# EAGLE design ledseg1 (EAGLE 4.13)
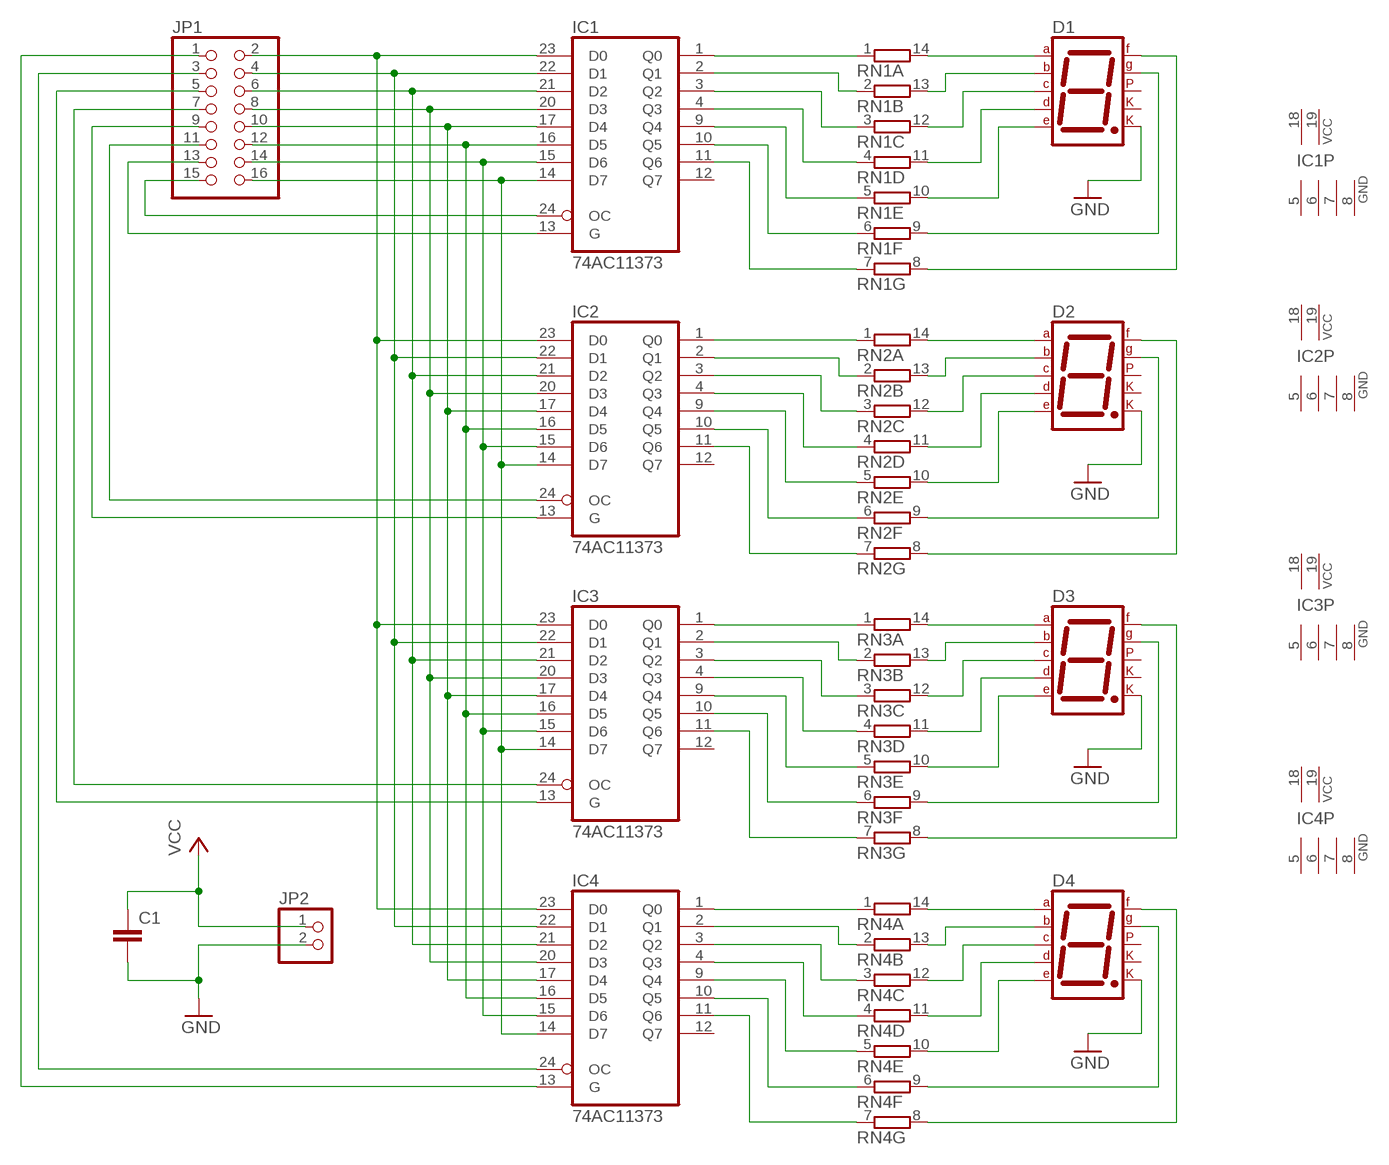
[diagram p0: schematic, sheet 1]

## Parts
C1  C-EU025-030X050  [C025-030X050]
D1  7SEG-CK  [7SEG-13]
D2  7SEG-CK  [7SEG-13]
D3  7SEG-CK  [7SEG-13]
D4  7SEG-CK  [7SEG-13]
IC1  74AC11373  [DIL24-6]
IC2  74AC11373  [DIL24-6]
IC3  74AC11373  [DIL24-6]
IC4  74AC11373  [DIL24-6]
JP1  PINHD-2X8  [2X08]
JP2  PINHD-1X2  [1X02]
RN1  7R-N  [DIL14]
RN2  7R-N  [DIL14]
RN3  7R-N  [DIL14]
RN4  7R-N  [DIL14]

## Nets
D0: IC1.23(D0) IC2.23(D0) IC3.23(D0) IC4.23(D0) JP1.2
D1: IC1.22(D1) IC2.22(D1) IC3.22(D1) IC4.22(D1) JP1.4
D2: IC1.21(D2) IC2.21(D2) IC3.21(D2) IC4.21(D2) JP1.6
D3: IC1.20(D3) IC2.20(D3) IC3.20(D3) IC4.20(D3) JP1.8
D4: IC1.17(D4) IC2.17(D4) IC3.17(D4) IC4.17(D4) JP1.10
D5: IC1.16(D5) IC2.16(D5) IC3.16(D5) IC4.16(D5) JP1.12
D6: IC1.15(D6) IC2.15(D6) IC3.15(D6) IC4.15(D6) JP1.14
D7: IC1.14(D7) IC2.14(D7) IC3.14(D7) IC4.14(D7) JP1.16
GND: C1.2 D1.8(CK2) D2.8(CK2) D3.8(CK2) D4.8(CK2) JP2.2
N$1: D1.7(A) RN1.14
N$2: D1.6(B) RN1.13
N$3: D1.4(C) RN1.12
N$4: D1.2(D) RN1.11
N$5: D1.1(E) RN1.10
N$6: D1.10(G) RN1.9
N$7: D1.9(F) RN1.8
N$8: D2.7(A) RN2.14
N$9: D2.6(B) RN2.13
N$10: D2.4(C) RN2.12
N$11: D2.2(D) RN2.11
N$12: D2.1(E) RN2.10
N$13: D2.10(G) RN2.9
N$14: D2.9(F) RN2.8
N$15: D3.7(A) RN3.14
N$16: D3.6(B) RN3.13
N$17: D3.4(C) RN3.12
N$18: D3.2(D) RN3.11
N$19: D3.1(E) RN3.10
N$20: D3.10(G) RN3.9
N$21: D3.9(F) RN3.8
N$22: D4.7(A) RN4.14
N$23: D4.6(B) RN4.13
N$24: D4.4(C) RN4.12
N$25: D4.2(D) RN4.11
N$26: D4.1(E) RN4.10
N$27: D4.10(G) RN4.9
N$28: D4.9(F) RN4.8
N$29: IC4.1(Q0) RN4.1
N$30: IC4.2(Q1) RN4.2
N$31: IC4.3(Q2) RN4.3
N$32: IC1.1(Q0) RN1.1
N$33: IC1.2(Q1) RN1.2
N$34: IC1.3(Q2) RN1.3
N$35: IC1.4(Q3) RN1.4
N$36: IC1.9(Q4) RN1.5
N$37: IC1.10(Q5) RN1.6
N$38: IC1.11(Q6) RN1.7
N$39: IC2.1(Q0) RN2.1
N$40: IC2.2(Q1) RN2.2
N$41: IC2.3(Q2) RN2.3
N$42: IC2.4(Q3) RN2.4
N$43: IC2.9(Q4) RN2.5
N$44: IC2.10(Q5) RN2.6
N$45: IC2.11(Q6) RN2.7
N$46: IC3.1(Q0) RN3.1
N$47: IC3.2(Q1) RN3.2
N$48: IC3.3(Q2) RN3.3
N$49: IC3.4(Q3) RN3.4
N$50: IC3.9(Q4) RN3.5
N$51: IC3.10(Q5) RN3.6
N$52: IC3.11(Q6) RN3.7
N$53: IC4.4(Q3) RN4.4
N$54: IC4.9(Q4) RN4.5
N$55: IC4.10(Q5) RN4.6
N$56: IC4.11(Q6) RN4.7
N$57: IC2.24(OC) JP1.11
N$58: IC2.13(G) JP1.9
N$59: IC3.24(OC) JP1.7
N$60: IC3.13(G) JP1.5
N$61: IC4.24(OC) JP1.3
N$62: IC4.13(G) JP1.1
N$65: IC1.24(OC) JP1.15
N$66: IC1.13(G) JP1.13
VCC: C1.1 JP2.1
Unconnected: D1.3(CK1) D1.5(DP) D2.3(CK1) D2.5(DP) D3.3(CK1) D3.5(DP) D4.3(CK1) D4.5(DP) IC1.12(Q7) IC2.12(Q7) IC3.12(Q7) IC4.12(Q7)

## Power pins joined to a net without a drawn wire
GND: IC1.5(GND) IC1.6(GND) IC1.7(GND) IC1.8(GND) IC2.5(GND) IC2.6(GND) IC2.7(GND) IC2.8(GND) IC3.5(GND) IC3.6(GND) IC3.7(GND) IC3.8(GND) IC4.5(GND) IC4.6(GND) IC4.7(GND) IC4.8(GND)
VCC: IC1.18(VCC) IC1.19(VCC) IC2.18(VCC) IC2.19(VCC) IC3.18(VCC) IC3.19(VCC) IC4.18(VCC) IC4.19(VCC)

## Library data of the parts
C1 = rcl:C-EU: CAPACITOR, European symbol
D1-D4 = special:7SEG-CK: 7-segment DISPLAY single cathode, 13 mm
IC1-IC4 = 74ac-logic:74AC11373: Octal transparent D-type LATCH, 3-state
JP1 = pinhead:PINHD-2X8: PIN HEADER
JP2 = pinhead:PINHD-1X2: PIN HEADER
RN1-RN4 = resistor-dil:7R-N: DIL RESISTOR

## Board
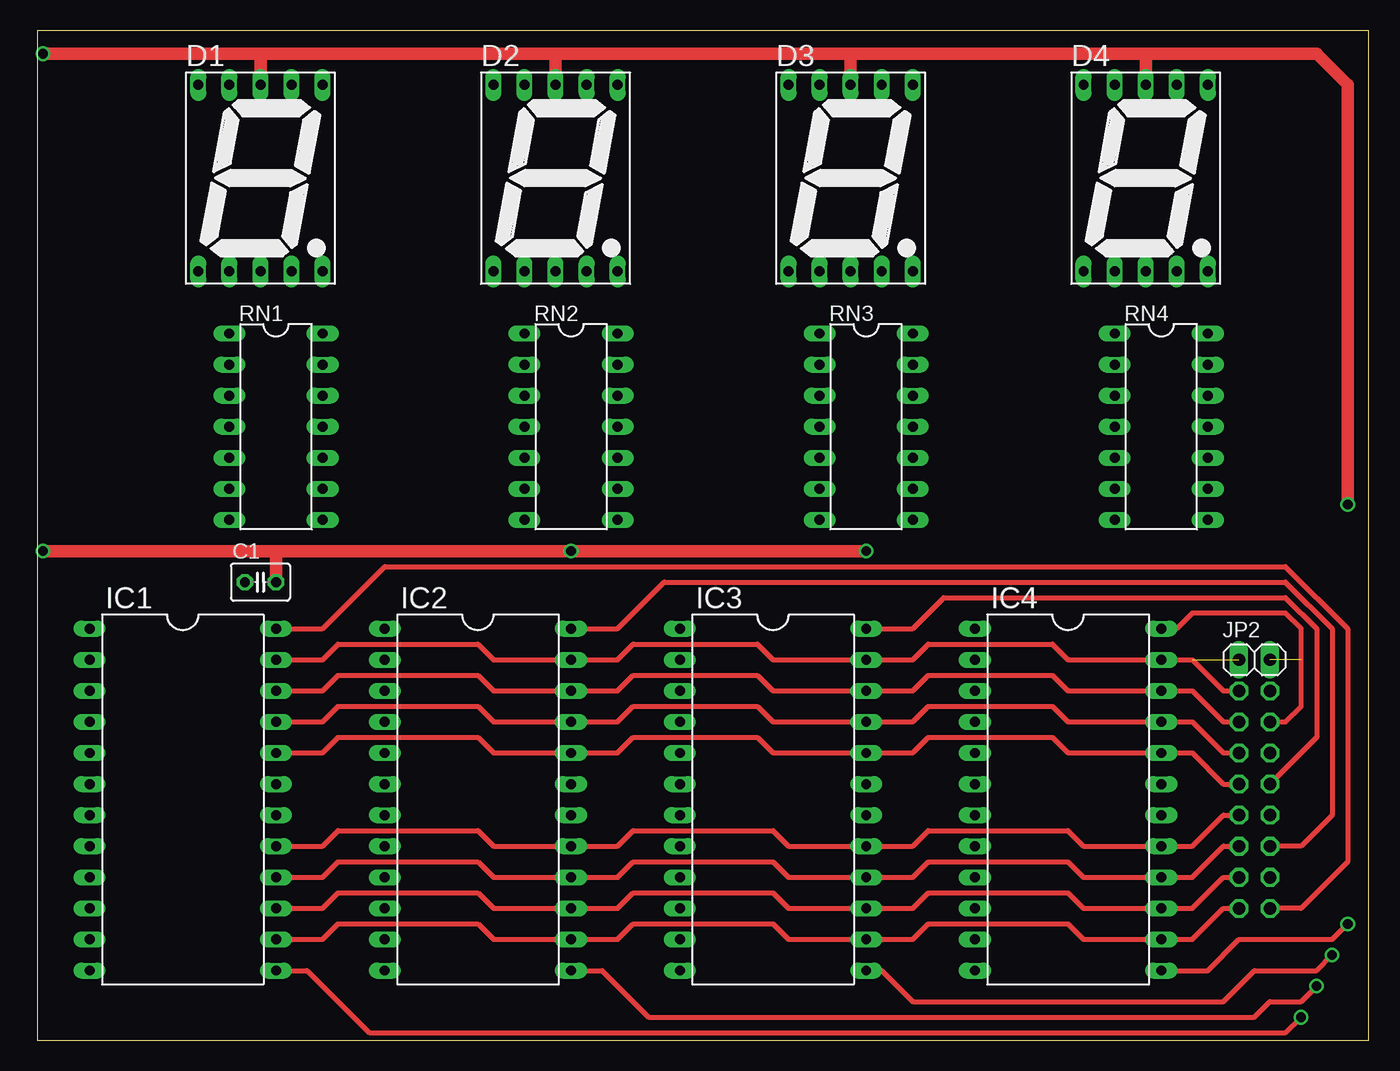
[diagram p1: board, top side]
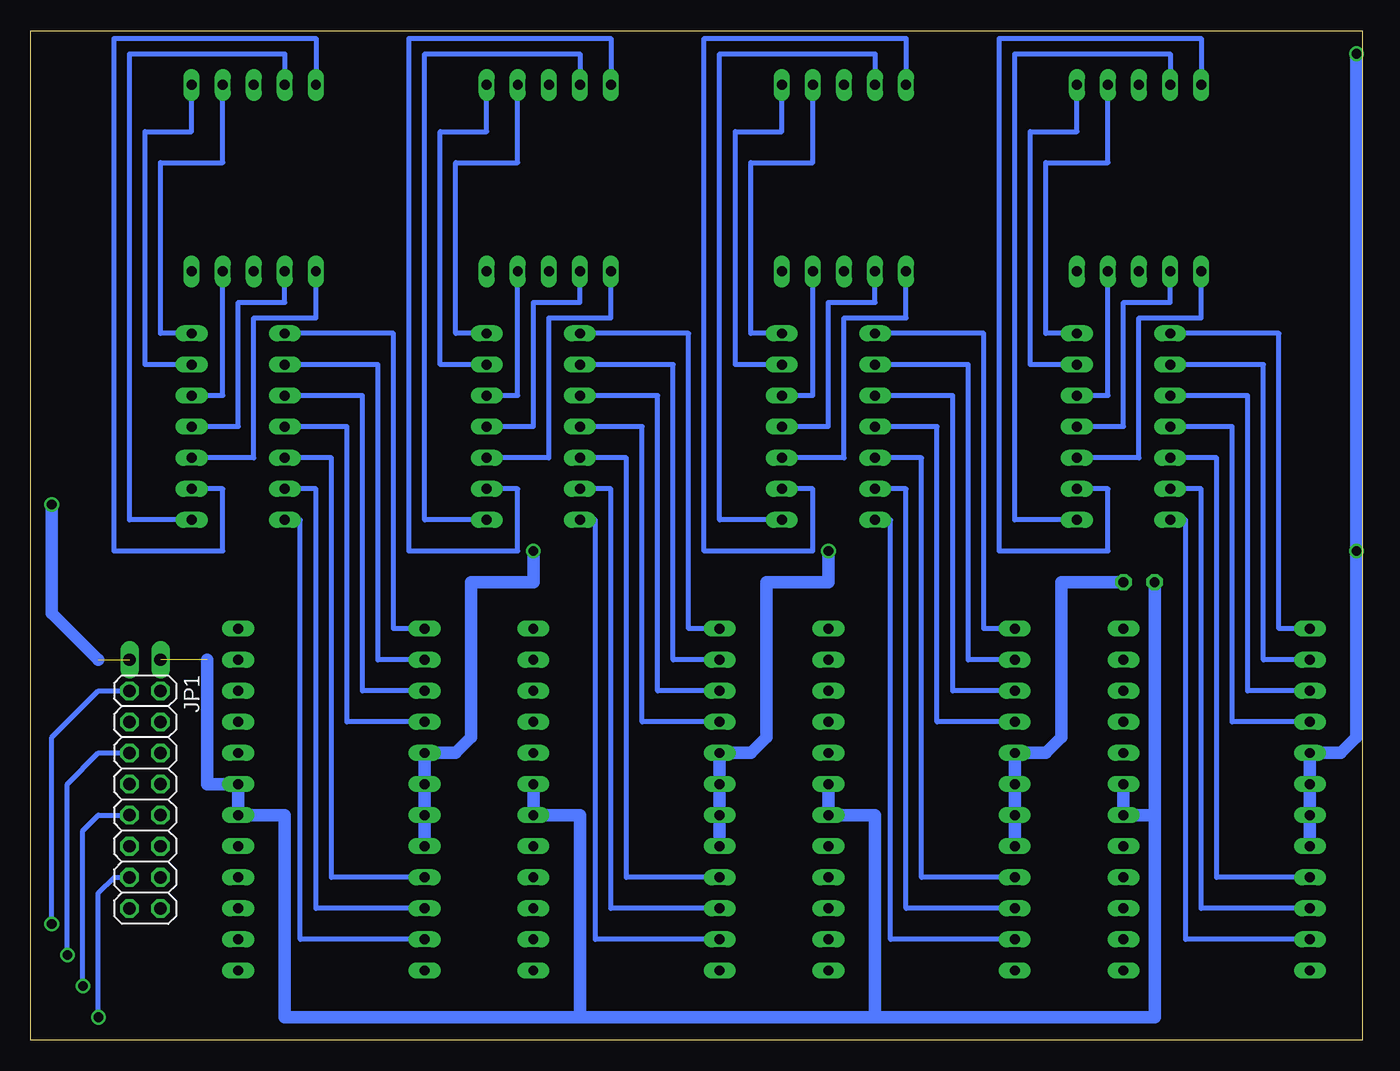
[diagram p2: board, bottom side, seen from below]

Size 108.89 x 82.54 mm. Coordinates in mm from the lower left corner, seen from the top.
Outline: 0,0 108.89,0 108.89,82.54 0,82.54 0,0
Copper layers (1*16): Top 0.035mm / dielectric 1.5mm / Bottom 0.035mm
Design rules "default": minimum track width 10mil, minimum drill 24mil, track to track 8mil, track to pad 8mil, pad to pad 8mil, via to via 8mil, smd to smd 8mil, copper to edge 40mil, drill to drill 8mil, minimum pad ring 10mil, minimum via ring 8mil, stop-mask expansion 4mil, vias tented up to drill 0mil, thermal gap 10mil

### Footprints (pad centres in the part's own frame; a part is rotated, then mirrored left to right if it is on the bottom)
C025-030X050 = drill 0.813 octagon: 1 -1.27,0; 2 1.27,0
7SEG-13 = drill 0.813 long: 1 -5.08,-7.62; 2 -2.54,-7.62; 3 0,-7.62; 4 2.54,-7.62; 5 5.08,-7.62; 6 5.08,7.62; 7 2.54,7.62; 8 0,7.62; 9 -2.54,7.62; 10 -5.08,7.62
DIL24-6 = drill 0.813 long: 1 -13.97,-7.62; 2 -11.43,-7.62; 3 -8.89,-7.62; 4 -6.35,-7.62; 5 -3.81,-7.62; 6 -1.27,-7.62; 7 1.27,-7.62; 8 3.81,-7.62; 9 6.35,-7.62; 10 8.89,-7.62; 11 11.43,-7.62; 12 13.97,-7.62; 13 13.97,7.62; 14 11.43,7.62; 15 8.89,7.62; 16 6.35,7.62; 17 3.81,7.62; 18 1.27,7.62; 19 -1.27,7.62; 20 -3.81,7.62; 21 -6.35,7.62; 22 -8.89,7.62; 23 -11.43,7.62; 24 -13.97,7.62
2X08 = drill 1.016 octagon: 1 -8.89,-1.27; 2 -8.89,1.27; 3 -6.35,-1.27; 4 -6.35,1.27; 5 -3.81,-1.27; 6 -3.81,1.27; 7 -1.27,-1.27; 8 -1.27,1.27; 9 1.27,-1.27; 10 1.27,1.27; 11 3.81,-1.27; 12 3.81,1.27; 13 6.35,-1.27; 14 6.35,1.27; 15 8.89,-1.27; 16 8.89,1.27
1X02 = drill 1.016 long: 1 -1.27,0; 2 1.27,0
DIL14 = drill 0.813 long: 1 -7.62,-3.81; 2 -5.08,-3.81; 3 -2.54,-3.81; 4 0,-3.81; 5 2.54,-3.81; 6 5.08,-3.81; 7 7.62,-3.81; 8 7.62,3.81; 9 5.08,3.81; 10 2.54,3.81; 11 0,3.81; 12 -2.54,3.81; 13 -5.08,3.81; 14 -7.62,3.81

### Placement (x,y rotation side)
C1  18.25,37.46 0 top
D1  18.25,70.48 0 top
D2  42.38,70.48 0 top
D3  66.51,70.48 0 top
D4  90.64,70.48 0 top
IC1  11.9,19.68 270 top
IC2  36.03,19.68 270 top
IC3  60.16,19.68 270 top
IC4  84.29,19.68 270 top
JP1  99.53,19.68 270 bottom
JP2  99.53,31.11 0 top
RN1  19.52,50.16 270 top
RN2  43.65,50.16 270 top
RN3  67.78,50.16 270 top
RN4  91.91,50.16 270 top

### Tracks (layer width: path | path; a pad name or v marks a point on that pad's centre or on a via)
D0
  Top 0.406: JP1.2 96.99,28.57 94.45,31.11 IC4.23 84.29,31.11 83.02,32.38 72.86,32.38 71.59,31.11 IC3.23 60.16,31.11 58.89,32.38 48.73,32.38 47.46,31.11 IC2.23 37.3,31.11 36.03,32.38 24.6,32.38 23.33,31.11 IC1.23
D1
  Top 0.406: JP1.4 96.99,26.03 94.45,28.57 IC4.22 84.29,28.57 83.02,29.84 72.86,29.84 71.59,28.57 IC3.22 60.16,28.57 58.89,29.84 48.73,29.84 47.46,28.57 IC2.22 37.3,28.57 36.03,29.84 24.6,29.84 23.33,28.57 IC1.22
D2
  Top 0.406: JP1.6 96.99,23.49 94.45,26.03 IC4.21 84.29,26.03 83.02,27.3 72.86,27.3 71.59,26.03 IC3.21 60.16,26.03 58.89,27.3 48.73,27.3 47.46,26.03 IC2.21 37.3,26.03 36.03,27.3 24.6,27.3 23.33,26.03 IC1.21
D3
  Top 0.406: JP1.8 96.99,20.95 94.45,23.49 IC4.20 84.29,23.49 83.02,24.76 72.86,24.76 71.59,23.49 IC3.20 60.16,23.49 58.89,24.76 48.73,24.76 47.46,23.49 IC2.20 37.3,23.49 36.03,24.76 24.6,24.76 23.33,23.49 IC1.20
D4
  Top 0.406: JP1.10 96.99,18.41 94.45,15.87 IC4.17 85.56,15.87 84.29,17.14 72.86,17.14 71.59,15.87 IC3.17 61.43,15.87 60.16,17.14 48.73,17.14 47.46,15.87 IC2.17 37.3,15.87 36.03,17.14 24.6,17.14 23.33,15.87 IC1.17
D5
  Top 0.406: JP1.12 96.99,15.87 94.45,13.33 IC4.16 85.56,13.33 84.29,14.6 72.86,14.6 71.59,13.33 IC3.16 61.43,13.33 60.16,14.6 48.73,14.6 47.46,13.33 IC2.16 37.3,13.33 36.03,14.6 24.6,14.6 23.33,13.33 IC1.16
D6
  Top 0.406: JP1.14 96.99,13.33 94.45,10.79 IC4.15 85.56,10.79 84.29,12.06 72.86,12.06 71.59,10.79 IC3.15 61.43,10.79 60.16,12.06 48.73,12.06 47.46,10.79 IC2.15 37.3,10.79 36.03,12.06 24.6,12.06 23.33,10.79 IC1.15
D7
  Top 0.406: JP1.16 96.99,10.79 94.45,8.25 IC4.14 85.56,8.25 84.29,9.52 72.86,9.52 71.59,8.25 IC3.14 61.43,8.25 60.16,9.52 48.73,9.52 47.46,8.25 IC2.14 37.3,8.25 36.03,9.52 24.6,9.52 23.33,8.25 IC1.14
GND  (via drill 0.8)  (1 unrouted)
  Top 1.016: 18.25,80.64 D1.8 | 18.25,80.64 42.38,80.64 | 42.38,80.64 66.51,80.64 | 66.51,80.64 90.64,80.64 | 90.64,80.64 D4.8 | 42.38,80.64 D2.8 | 66.51,80.64 D3.8 | v67.78,40 v43.65,40 19.52,40 | 19.52,40 C1.2 | v0.47,80.64 18.25,80.64 | v107.15,43.81 107.15,78.1 104.61,80.64 90.64,80.64 | v0.47,40 19.52,40
  Bottom 1.016: IC4.8 IC4.7 IC4.6 IC4.5 74.13,23.49 72.86,24.76 72.86,37.46 67.78,37.46 v67.78,40 | IC3.8 IC3.7 IC3.6 IC3.5 50,23.49 48.73,24.76 48.73,37.46 43.65,37.46 v43.65,40 | IC2.8 IC2.7 IC2.6 IC2.5 25.87,23.49 24.6,24.76 24.6,37.46 C1.2 | IC1.8 IC1.7 IC1.6 IC1.5 1.74,23.49 0.47,24.76 v0.47,40 v0.47,80.64 | v107.15,43.81 107.15,34.92 103.34,31.11
N$1
  Bottom 0.406: RN1.14 25.87,57.78 25.87,71.75 20.79,71.75 D1.7
N$2
  Bottom 0.406: D1.6 23.33,74.29 27.14,74.29 27.14,55.24 RN1.13
N$3
  Bottom 0.406: D1.4 20.79,52.7 RN1.12
N$4
  Bottom 0.406: RN1.11 19.52,50.16 19.52,60.32 15.71,60.32 D1.2
N$5
  Bottom 0.406: D1.1 13.17,59.05 18.25,59.05 18.25,47.62 RN1.10
N$6
  Bottom 0.406: D1.10 13.17,81.91 29.68,81.91 29.68,40 20.79,40 20.79,45.08 RN1.9
N$7
  Bottom 0.406: D1.9 15.71,80.64 28.41,80.64 28.41,42.54 RN1.8
N$8
  Bottom 0.406: RN2.14 50,57.78 50,71.75 44.92,71.75 D2.7
N$9
  Bottom 0.406: D2.6 47.46,74.29 51.27,74.29 51.27,55.24 RN2.13
N$10
  Bottom 0.406: D2.4 44.92,52.7 RN2.12
N$11
  Bottom 0.406: RN2.11 43.65,50.16 43.65,60.32 39.84,60.32 D2.2
N$12
  Bottom 0.406: D2.1 37.3,59.05 42.38,59.05 42.38,47.62 RN2.10
N$13
  Bottom 0.406: D2.10 37.3,81.91 53.81,81.91 53.81,40 44.92,40 44.92,45.08 RN2.9
N$14
  Bottom 0.406: D2.9 39.84,80.64 52.54,80.64 52.54,42.54 RN2.8
N$15
  Bottom 0.406: D3.7 69.05,71.75 74.13,71.75 74.13,57.78 RN3.14
N$16
  Bottom 0.406: D3.6 71.59,74.29 75.4,74.29 75.4,55.24 RN3.13
N$17
  Bottom 0.406: D3.4 69.05,52.7 RN3.12
N$18
  Bottom 0.406: RN3.11 67.78,50.16 67.78,60.32 63.97,60.32 D3.2
N$19
  Bottom 0.406: D3.1 61.43,59.05 66.51,59.05 66.51,47.62 RN3.10
N$20
  Bottom 0.406: D3.10 61.43,81.91 77.94,81.91 77.94,40 69.05,40 69.05,45.08 RN3.9
N$21
  Bottom 0.406: D3.9 63.97,80.64 76.67,80.64 76.67,42.54 RN3.8
N$22
  Bottom 0.406: D4.7 93.18,71.75 98.26,71.75 98.26,57.78 RN4.14
N$23
  Bottom 0.406: D4.6 95.72,74.29 99.53,74.29 99.53,55.24 RN4.13
N$24
  Bottom 0.406: D4.4 93.18,52.7 RN4.12
N$25
  Bottom 0.406: D4.2 88.1,60.32 91.91,60.32 91.91,50.16 RN4.11
N$26
  Bottom 0.406: RN4.10 90.64,47.62 90.64,59.05 85.56,59.05 D4.1
N$27
  Bottom 0.406: D4.10 85.56,81.91 102.07,81.91 102.07,40 93.18,40 93.18,45.08 RN4.9
N$28
  Bottom 0.406: D4.9 88.1,80.64 100.8,80.64 100.8,42.54 RN4.8
N$29
  Bottom 0.406: RN4.1 79.21,57.78 79.21,33.65 IC4.1
N$30
  Bottom 0.406: RN4.2 80.48,55.24 80.48,31.11 IC4.2
N$31
  Bottom 0.406: RN4.3 81.75,52.7 81.75,28.57 IC4.3
N$32
  Bottom 0.406: RN1.1 6.82,57.78 6.82,33.65 IC1.1
N$33
  Bottom 0.406: IC1.2 8.09,31.11 8.09,55.24 RN1.2
N$34
  Bottom 0.406: RN1.3 9.36,52.7 9.36,28.57 IC1.3
N$35
  Bottom 0.406: IC1.4 10.63,26.03 10.63,50.16 RN1.4
N$36
  Bottom 0.406: IC1.9 11.9,13.33 11.9,47.62 RN1.5
N$37
  Bottom 0.406: IC1.10 13.17,10.79 13.17,45.08 RN1.6
N$38
  Bottom 0.406: IC1.11 14.44,8.25 14.44,42.54 RN1.7
N$39
  Bottom 0.406: IC2.1 30.95,33.65 30.95,57.78 RN2.1
N$40
  Bottom 0.406: RN2.2 32.22,55.24 32.22,31.11 IC2.2
N$41
  Bottom 0.406: RN2.3 33.49,52.7 33.49,28.57 IC2.3
N$42
  Bottom 0.406: RN2.4 34.76,50.16 34.76,26.03 IC2.4
N$43
  Bottom 0.406: RN2.5 36.03,47.62 36.03,13.33 IC2.9
N$44
  Bottom 0.406: RN2.6 37.3,45.08 37.3,10.79 IC2.10
N$45
  Bottom 0.406: RN2.7 38.57,42.54 38.57,8.25 IC2.11
N$46
  Bottom 0.406: RN3.1 55.08,57.78 55.08,33.65 IC3.1
N$47
  Bottom 0.406: IC3.2 56.35,31.11 56.35,55.24 RN3.2
N$48
  Bottom 0.406: RN3.3 57.62,52.7 57.62,28.57 IC3.3
N$49
  Bottom 0.406: RN3.4 58.89,50.16 58.89,26.03 IC3.4
N$50
  Bottom 0.406: RN3.5 60.16,47.62 60.16,13.33 IC3.9
N$51
  Bottom 0.406: RN3.6 61.43,45.08 61.43,10.79 IC3.10
N$52
  Bottom 0.406: RN3.7 62.7,42.54 62.7,8.25 IC3.11
N$53
  Bottom 0.406: RN4.4 83.02,50.16 83.02,26.03 IC4.4
N$54
  Bottom 0.406: RN4.5 84.29,47.62 84.29,13.33 IC4.9
N$55
  Bottom 0.406: RN4.6 85.56,45.08 85.56,10.79 IC4.10
N$56
  Bottom 0.406: RN4.7 86.83,42.54 86.83,8.25 IC4.11
N$57
  Top 0.406: IC2.24 47.46,33.65 51.27,37.46 102.07,37.46 105.88,33.65 105.88,18.41 103.34,15.87 JP1.11
N$58  (via drill 0.8)
  Top 0.406: IC2.13 46.19,5.71 50,1.9 99.53,1.9 100.8,3.17 103.34,3.17 v104.61,4.44
  Bottom 0.406: JP1.9 103.34,18.41 104.61,17.14 v104.61,4.44
N$59
  Top 0.406: IC3.24 71.59,33.65 74.13,36.19 102.07,36.19 104.61,33.65 104.61,24.76 JP1.7
N$60  (via drill 0.8)
  Top 0.406: IC3.13 69.05,5.71 71.59,3.17 96.99,3.17 99.53,5.71 104.61,5.71 v105.88,6.98
  Bottom 0.406: JP1.5 103.34,23.49 105.88,20.95 v105.88,6.98
N$61
  Top 0.406: IC4.24 93.18,33.65 94.45,34.92 102.07,34.92 103.34,33.65 103.34,27.3 102.07,26.03 JP1.3
N$62  (via drill 0.8)
  Top 0.406: IC4.13 95.72,5.71 98.26,8.25 105.88,8.25 v107.15,9.52
  Bottom 0.406: JP1.1 103.34,28.57 107.15,24.76 v107.15,9.52
N$65
  Top 0.406: IC1.24 23.33,33.65 28.41,38.73 102.07,38.73 107.15,33.65 107.15,14.6 103.34,10.79 JP1.15
N$66  (via drill 0.8)
  Top 0.406: IC1.13 22.06,5.71 27.14,0.63 102.07,0.63 v103.34,1.9
  Bottom 0.406: v103.34,1.9 103.34,12.06 102.07,13.33 JP1.13
VCC  (1 unrouted)
  Bottom 1.016: IC1.19 IC1.18 16.98,18.41 | 16.98,18.41 16.98,1.9 39.84,1.9 | 39.84,1.9 63.97,1.9 | 63.97,1.9 88.1,1.9 88.1,18.41 IC4.18 IC4.19 94.45,20.95 94.45,31.11 | IC2.19 IC2.18 39.84,18.41 39.84,1.9 | 63.97,1.9 63.97,18.41 IC3.18 IC3.19 | 16.98,18.41 C1.1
